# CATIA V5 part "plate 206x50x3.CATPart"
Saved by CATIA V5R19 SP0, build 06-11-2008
Part number: plate 206x50x3
Bounding box of the stored display mesh (mm): x -206 to 0, y 0 to 3, z 0 to 50
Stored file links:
  D:\AUTO BATCH (BHEL)\Collecting Hopper 2\plate 206x50x3.CATPart
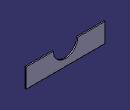
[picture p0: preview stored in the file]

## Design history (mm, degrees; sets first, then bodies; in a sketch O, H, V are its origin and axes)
SheetMetalParameters1: BendRadius 3, ReliefAxialLength 2, ReliefRadialLength 1, MinimumBendRadius 0, Thickness 3, KFactor 0.325257 {= log(min(100,max(20*SheetMetalParameters1.BendRadius,SheetMetalParameters1.Thickness)/SheetMetalParameters1.Thickness))/log(100)/2}
Body1 (main body)
  Sketch1 on zx-plane, origin (0, 0, 0), H (-1, 0, 0), V (0, 0, 1)
    line L1 (0, 0) -> (206, 0)
    line L2 (206, 0) -> (206, 50)
    line L3 (206, 50) -> (0, 50)
    line L4 (0, 50) -> (0, 0)
    length L1 = 206
    length L2 = 50
    horizontal: L1 H, L3 H
    vertical: L2 V, L4 V
  Wall1: Thickness 3, Profile Sketch1
  Sketch2 on face of Wall1, origin (0, 3, 0), H (-1, 0, 0), V (0, 0, 1)
    circle A1 centre (103, 50) radius 32
    point P1 (103, 50)
    reference projected line E1 (306, 50) -> (0, 50) from edge [face of Wall1 | face of Wall1]
    reference projected line E2 (0, 50) -> (0, 0) from edge [face of Wall1 | face of Wall1]
    radius A1 = 32
    distance P1 E2 = 103
    coincidence: P1 E1
  CutOut1: StartLimit through (limit type 2), Orientation true, Profile Sketch2, Direction Sketch2, EndLimit through (limit type 2)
